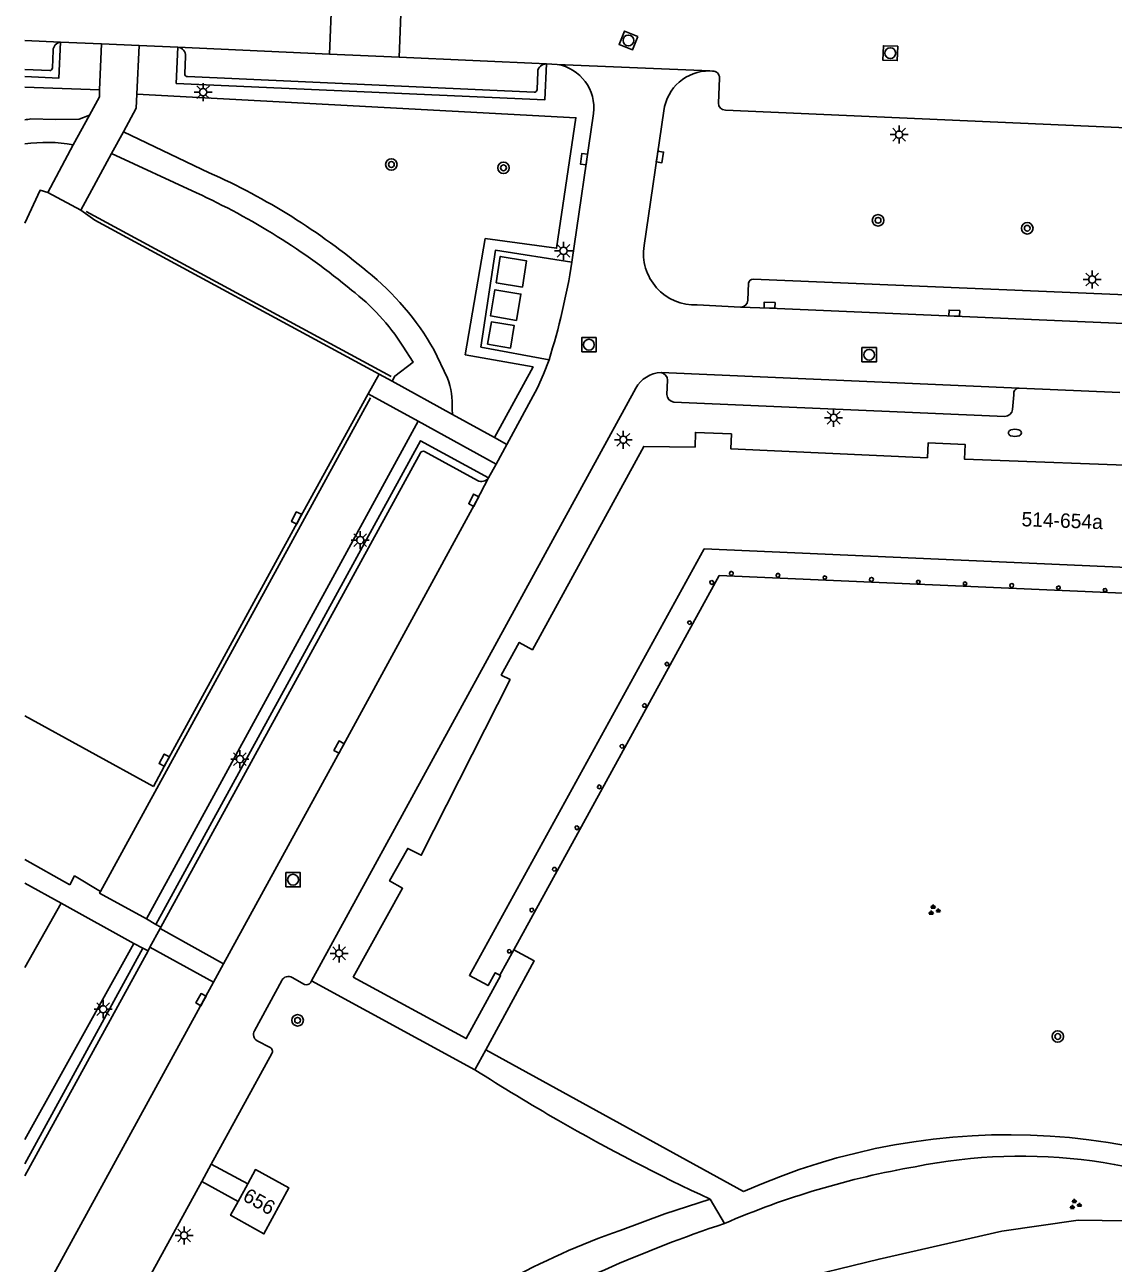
# Model space of a CAD drawing. Extents: x 132994 to 136000, y 393499 to 395512.
# Drawn here: x 133000 to 133075.7, y 395099.1 to 395185.2 of the extents above; entities that cross this region are included whole.
import ezdxf

# ---------------------------------------------------------------- set-up
doc = ezdxf.new("R2010")
doc.units = 0
for name, color, linetype in [('gg-afsc-hekwerk', 7, 'Continuous'), ('gg-anno-huisnummerreeks BGT', 7, 'Continuous'), ('gg-bbg-hoofdgebouw', 7, 'Continuous'), ('gg-bbg-onder overbouw', 7, 'Continuous'), ('gg-bbg-pand overbouw', 7, 'Continuous'), ('gg-bbg-pilaar onder overbouw', 7, 'Continuous'), ('gg-knt-verharding', 7, 'Continuous'), ('gg-knt-verharding nz', 7, 'Continuous'), ('gg-kntw-bovenkant insteek waterloop', 7, 'Continuous'), ('gg-kwrk-afval apart plaats', 7, 'Continuous'), ('gt-grn-groengrens', 7, 'Continuous'), ('gt-grn-weggrens', 7, 'Continuous'), ('gt-symb-boom', 7, 'Continuous'), ('gt-symb-brandkraan', 7, 'Continuous'), ('gt-symb-groenvak', 7, 'Continuous'), ('gt-symb-kolk', 7, 'Continuous'), ('gt-symb-lichtmast', 7, 'Continuous'), ('gt-symb-rioolschacht', 7, 'Continuous')]:
    doc.layers.add(name, color=color, linetype=linetype)

# ---------------------------------------------------------------- blocks, each defined once
blk = doc.blocks.new('gt0-BOOM')
at = {"layer": 'gt-symb-boom'}
for radius in [0.4, 0.2]:
    blk.add_circle((0, 0), radius, dxfattribs=at)
blk = doc.blocks.new('gt0-RS')
at = {"layer": 'gt-symb-rioolschacht'}
blk.add_lwpolyline([(-0.5, -0.5), (0.5, -0.5), (0.5, 0.5), (-0.5, 0.5)], close=True, dxfattribs=at)
blk.add_circle((0, 0), 0.375, dxfattribs=at)
blk = doc.blocks.new('gt0-KOLK')
at = {"layer": 'gt-symb-kolk'}
blk.add_lwpolyline([(0, 0), (0.375, 0), (0.375, 0.4), (-0.375, 0.4), (-0.375, 0), (0, 0)], dxfattribs=at)
blk = doc.blocks.new('gt0-LMAST')
at = {"layer": 'gt-symb-lichtmast'}
for p, q in [((-0.182, 0.173), (-0.447, 0.438)), ((-0.005, 0.246), (-0.005, 0.621)), ((0.172, 0.173), (0.437, 0.438)), ((-0.255, -0.004), (-0.63, -0.004)), ((-0.182, -0.181), (-0.447, -0.446)), ((-0.005, -0.254), (-0.005, -0.629)), ((0.437, -0.446), (0.172, -0.181)), ((0.245, -0.004), (0.62, -0.004))]:
    blk.add_line(p, q, dxfattribs=at)
blk.add_circle((-0.005, -0.004), 0.25, dxfattribs=at)
blk = doc.blocks.new('gt0-BR')
at = {"layer": 'gt-symb-brandkraan'}
for centre, radius, start, end in [((-0.244, 0), 0.206, 107.56694, 252.43307), ((0.599, -2.664), 3, 106.89205, 107.56694), ((0, -0.691), 0.938, 73.10799, 106.89205), ((-0.599, -2.664), 3, 72.43309, 73.10799), ((0.244, 0), 0.206, 287.56695, 72.43309), ((0.599, 2.664), 3, 252.43307, 253.10797), ((0, 0.691), 0.938, 253.10797, 286.89206), ((-0.599, 2.664), 3, 286.89206, 287.56695)]:
    blk.add_arc(centre, radius, start, end, dxfattribs=at)
blk = doc.blocks.new('gt0-GRVAK')
at = {"layer": 'gt-symb-groenvak'}
for p, q in [((-0.11, 0.189), (-0.228, 0.24)), ((-0.182, 0.153), (0.088, 0.153)), ((-0.091, 0.211), (-0.156, 0.322)), ((-0.047, 0.214), (-0.047, 0.393)), ((-0.004, 0.211), (0.061, 0.322)), ((0.015, 0.189), (0.133, 0.24)), ((0.262, -0.052), (0.197, 0.059)), ((0.305, -0.049), (0.305, 0.13)), ((0.349, -0.052), (0.414, 0.059)), ((-0.245, -0.228), (-0.363, -0.177)), ((-0.318, -0.264), (-0.047, -0.264)), ((-0.226, -0.206), (-0.291, -0.095)), ((-0.183, -0.203), (-0.183, -0.024)), ((-0.139, -0.206), (-0.074, -0.095)), ((-0.12, -0.228), (-0.002, -0.177)), ((0.243, -0.074), (0.125, -0.023)), ((0.17, -0.11), (0.441, -0.11)), ((0.368, -0.074), (0.486, -0.023))]:
    blk.add_line(p, q, dxfattribs=at)

msp = doc.modelspace()

# ---------------------------------------------------------------- linework, layer by layer
at = {"layer": 'gg-afsc-hekwerk'}
for p, q in [((133025.474, 395160.771), (133004.267, 395172.22)), ((133005.27, 395124.983), (133024.044, 395159.285)), ((133000, 395127.185), (133003.124, 395125.446))]:
    msp.add_line(p, q, dxfattribs=at)
at = {"layer": 'gg-bbg-hoofdgebouw'}
msp.add_line((133014.838, 395103.44), (133015.497, 395104.651), dxfattribs=at)
for points in [[(133078.98, 395154.5), (133065.33, 395155.01), (133065.37, 395156.04), (133062.8, 395156.14), (133062.75, 395155.11), (133049.08, 395155.74), (133049.13, 395156.77), (133046.62, 395156.88), (133046.6, 395155.85), (133043.03, 395155.9), (133035.29, 395141.77), (133034.38, 395142.28), (133033.13, 395140.01), (133033.74, 395139.7), (133027.56, 395127.49), (133026.62, 395127.97), (133025.36, 395125.71), (133026.26, 395125.2), (133022.83, 395119.03)], [(133033.025, 395119.153), (133033.081, 395119.122), (133030.694, 395114.746), (133022.83, 395119.03)], [(133015.497, 395104.651), (133016.04, 395105.65), (133018.35, 395104.39), (133016.62, 395101.18), (133014.311, 395102.47), (133014.838, 395103.44)]]:
    msp.add_lwpolyline(points, dxfattribs=at)
at = {"layer": 'gg-bbg-onder overbouw'}
msp.add_lwpolyline([(133108.047, 395115.865), (133108.381, 395116.009), (133108.775, 395115.09), (133110.117, 395115.666), (133108.342, 395119.716), (133096.637, 395146.616), (133047.236, 395148.781), (133030.913, 395119.145), (133032.209, 395118.431), (133032.704, 395119.33), (133033.025, 395119.153)], dxfattribs=at)
at = {"layer": 'gg-bbg-pand overbouw'}
msp.add_line((133033.025, 395119.153), (133033.99, 395120.909), dxfattribs=at)
msp.add_lwpolyline([(133033.99, 395120.909), (133048.281, 395146.92), (133095.419, 395144.881), (133107.382, 395117.393)], dxfattribs=at)
at = {"layer": 'gg-bbg-pilaar onder overbouw'}
for points in [[(133047.773, 395146.583), (133047.849, 395146.547), (133047.889, 395146.473), (133047.854, 395146.355), (133047.78, 395146.315), (133047.662, 395146.35), (133047.621, 395146.466), (133047.657, 395146.542), (133047.773, 395146.583)], [(133048.985, 395147.101), (133049.055, 395147.202), (133049.137, 395147.217), (133049.238, 395147.147), (133049.241, 395147.025), (133049.183, 395146.964), (133049.061, 395146.961), (133049, 395147.019), (133048.985, 395147.101)], [(133052.492, 395146.926), (133052.423, 395146.826), (133052.301, 395146.823), (133052.241, 395146.88), (133052.226, 395146.962), (133052.295, 395147.062), (133052.417, 395147.065), (133052.477, 395147.008), (133052.492, 395146.926)], [(133055.742, 395146.765), (133055.677, 395146.671), (133055.53, 395146.691), (133055.503, 395146.836), (133055.594, 395146.906), (133055.728, 395146.842), (133055.742, 395146.765)], [(133058.991, 395146.643), (133058.954, 395146.566), (133058.835, 395146.524), (133058.758, 395146.561), (133058.717, 395146.636), (133058.753, 395146.757), (133058.872, 395146.799), (133058.949, 395146.762), (133058.991, 395146.643)], [(133062.235, 395146.466), (133062.201, 395146.396), (133062.092, 395146.357), (133061.984, 395146.46), (133062.049, 395146.594), (133062.196, 395146.575), (133062.235, 395146.466)], [(133065.468, 395146.426), (133065.486, 395146.35), (133065.389, 395146.238), (133065.253, 395146.295), (133065.265, 395146.442), (133065.371, 395146.486), (133065.468, 395146.426)], [(133068.737, 395146.271), (133068.713, 395146.152), (133068.643, 395146.106), (133068.524, 395146.13), (133068.473, 395146.241), (133068.533, 395146.348), (133068.613, 395146.37), (133068.691, 395146.341), (133068.737, 395146.271)], [(133071.985, 395146.127), (133071.99, 395146.047), (133071.871, 395145.951), (133071.763, 395145.999), (133071.734, 395146.074), (133071.755, 395146.152), (133071.898, 395146.207), (133071.985, 395146.127)], [(133075.211, 395145.982), (133075.215, 395145.865), (133075.081, 395145.792), (133074.971, 395145.896), (133075.004, 395146.009), (133075.153, 395146.037), (133075.211, 395145.982)], [(133046.337, 395143.639), (133046.303, 395143.567), (133046.193, 395143.528), (133046.083, 395143.632), (133046.148, 395143.768), (133046.298, 395143.749), (133046.337, 395143.639)], [(133044.535, 395140.847), (133044.639, 395140.902), (133044.763, 395140.814), (133044.718, 395140.669), (133044.602, 395140.649), (133044.511, 395140.771), (133044.535, 395140.847)], [(133043.188, 395137.838), (133043.13, 395137.783), (133043.012, 395137.787), (133042.957, 395137.845), (133042.947, 395137.925), (133043.058, 395138.029), (133043.192, 395137.956), (133043.188, 395137.838)], [(133041.39, 395135.027), (133041.39, 395135.108), (133041.438, 395135.174), (133041.556, 395135.193), (133041.641, 395135.108), (133041.641, 395135.027), (133041.593, 395134.961), (133041.475, 395134.942), (133041.39, 395135.027)], [(133039.855, 395132.342), (133039.93, 395132.373), (133040.061, 395132.292), (133040.025, 395132.142), (133039.95, 395132.111), (133039.84, 395132.157), (133039.809, 395132.232), (133039.855, 395132.342)], [(133038.386, 395129.532), (133038.495, 395129.476), (133038.521, 395129.397), (133038.495, 395129.317), (133038.386, 395129.261), (133038.276, 395129.317), (133038.257, 395129.438), (133038.306, 395129.506), (133038.386, 395129.532)], [(133036.885, 395126.644), (133036.941, 395126.582), (133036.935, 395126.46), (133036.873, 395126.404), (133036.79, 395126.395), (133036.695, 395126.472), (133036.701, 395126.594), (133036.763, 395126.65), (133036.885, 395126.644)], [(133035.244, 395123.822), (133035.322, 395123.797), (133035.37, 395123.731), (133035.37, 395123.649), (133035.285, 395123.564), (133035.203, 395123.564), (133035.137, 395123.612), (133035.137, 395123.768), (133035.244, 395123.822)], [(133033.607, 395120.919), (133033.723, 395120.94), (133033.808, 395120.858), (133033.764, 395120.712), (133033.611, 395120.709), (133033.561, 395120.853), (133033.607, 395120.919)]]:
    msp.add_lwpolyline(points, dxfattribs=at)
at = {"layer": 'gg-knt-verharding'}
for p, q in [((133021.424, 395188.984), (133021.189, 395183.16)), ((133026.023, 395182.955), (133026.266, 395188.757)), ((133000, 395184.106), (133002.484, 395183.997)), ((133002.484, 395183.997), (133005.332, 395183.878)), ((133005.207, 395180.675), (133005.332, 395183.878)), ((133005.332, 395183.878), (133007.964, 395183.763)), ((133007.964, 395183.763), (133007.8, 395180.384)), ((133007.964, 395183.763), (133010.645, 395183.642)), ((133010.645, 395183.642), (133021.189, 395183.16)), ((133001.922, 395182.21), (133001.966, 395183.417)), ((133011.178, 395183.022), (133011.124, 395181.79)), ((133021.189, 395183.16), (133026.023, 395182.955)), ((133026.023, 395182.955), (133036.26, 395182.483)), ((133000, 395182.1), (133001.735, 395182.024)), ((133035.617, 395180.708), (133035.656, 395181.943)), ((133036.26, 395182.483), (133037.017, 395182.451)), ((133037.017, 395182.451), (133047.625, 395181.995)), ((133047.807, 395181.987), (133047.625, 395181.995)), ((133011.302, 395181.596), (133035.407, 395180.511)), ((133048.289, 395181.5), (133048.221, 395179.761)), ((133004.498, 395178.912), (133003.361, 395176.869)), ((133038.033, 395168.697), (133039.542, 395179.044)), ((133044.426, 395179.225), (133043.053, 395169.855)), ((133048.702, 395179.263), (133099.188, 395177.053)), ((133006.861, 395177.758), (133006.022, 395176.249)), ((133006.861, 395177.758), (133012.83, 395174.918)), ((133003.361, 395176.869), (133001.594, 395173.545)), ((133006.022, 395176.249), (133003.893, 395172.308)), ((133006.022, 395176.249), (133011.937, 395173.517)), ((133003.893, 395172.308), (133001.594, 395173.545)), ((133050.276, 395166.054), (133050.32, 395167.245)), ((133050.627, 395167.533), (133097.55, 395165.532)), ((133046.738, 395165.731), (133049.764, 395165.575)), ((133028.44, 395162.628), (133029.382, 395160.65)), ((133024.64, 395160.922), (133023.874, 395159.556)), ((133024.64, 395160.922), (133025.534, 395160.437)), ((133025.534, 395160.437), (133029.727, 395158.123)), ((133044.686, 395160.498), (133044.646, 395159.518)), ((133019.939, 395118.762), (133042.489, 395159.941)), ((133023.874, 395159.556), (133027.339, 395157.646)), ((133068.676, 395158.456), (133068.761, 395159.492)), ((133069.131, 395159.96), (133076.121, 395159.646)), ((133045.115, 395158.987), (133068.137, 395157.991)), ((133029.712, 395158.486), (133029.727, 395158.123)), ((133029.727, 395158.123), (133032.666, 395156.523)), ((133027.339, 395157.646), (133032.771, 395154.673)), ((133032.666, 395156.523), (133033.51, 395156.036)), ((133032.771, 395154.673), (133033.51, 395156.036)), ((133009.46, 395122.485), (133027.507, 395155.45)), ((133027.789, 395155.547), (133031.469, 395153.524)), ((133032.237, 395153.707), (133032.771, 395154.673)), ((133000, 395137.182), (133008.958, 395132.275)), ((133000, 395125.553), (133002.54, 395124.155)), ((133000, 395119.68), (133002.54, 395124.155)), ((133002.54, 395124.155), (133007.586, 395121.365)), ((133009.112, 395122.69), (133008.452, 395123.08)), ((133009.112, 395122.69), (133009.46, 395122.485)), ((133009.408, 395122.391), (133009.46, 395122.485)), ((133008.69, 395121.1), (133009.408, 395122.391)), ((133000, 395106.049), (133008.209, 395121.041)), ((133000, 395105.209), (133008.571, 395120.852)), ((133008.209, 395121.041), (133007.586, 395121.365)), ((133008.209, 395121.041), (133008.571, 395120.852)), ((133008.571, 395120.852), (133008.69, 395121.1)), ((133015.965, 395115.285), (133017.866, 395118.792)), ((133018.59, 395118.999), (133019.452, 395118.519)), ((133019.872, 395118.63), (133019.939, 395118.762)), ((133019.939, 395118.762), (133031.293, 395112.584)), ((133017.051, 395114.13), (133016.149, 395114.604)), ((133031.293, 395112.584), (133032.047, 395113.974)), ((133049.967, 395104.115), (133032.047, 395113.974)), ((133012.965, 395106.027), (133017.181, 395113.713)), ((133012.304, 395104.817), (133012.965, 395106.027)), ((133012.965, 395106.027), (133015.497, 395104.651)), ((133003.374, 395088.526), (133012.304, 395104.817)), ((133012.304, 395104.817), (133014.838, 395103.44))]:
    msp.add_line(p, q, dxfattribs=at)
for points in [[(133000, 395181.599), (133002.375, 395181.496), (133002.484, 395183.997)], [(133010.645, 395183.642), (133010.532, 395181.13), (133036.147, 395179.977), (133036.26, 395182.483)], [(133004.498, 395178.912), (133005.189, 395180.205), (133005.207, 395180.675)], [(133007.8, 395180.384), (133007.737, 395179.415), (133006.861, 395177.758)], [(133000.431, 395178.658), (133002.105, 395178.628), (133003.785, 395178.632), (133004.498, 395178.912)], [(133000, 395171.413), (133001.07, 395173.706), (133001.594, 395173.545)], [(133003.893, 395172.308), (133004.875, 395171.634), (133024.64, 395160.922)], [(133036.444, 395161.912), (133031.71, 395162.809), (133032.734, 395169.55), (133038.033, 395168.697)], [(133026.28, 395162.878), (133026.993, 395161.749), (133025.728, 395160.793), (133025.534, 395160.437)], [(133033.51, 395156.036), (133035.641, 395159.963), (133036.057, 395160.929), (133036.444, 395161.912)], [(133008.958, 395132.275), (133009.873, 395134), (133019.074, 395150.846), (133023.874, 395159.556)], [(133032.237, 395153.707), (133027.513, 395156.293), (133009.112, 395122.69)], [(133003.124, 395125.446), (133003.459, 395126.049), (133005.27, 395124.983)], [(133005.27, 395124.983), (133005.204, 395124.862), (133008.452, 395123.08)], [(133032.047, 395113.974), (133035.401, 395120.154), (133033.99, 395120.909)], [(133047.638, 395103.593), (133044.485, 395102.574), (133041.38, 395101.418)]]:
    msp.add_lwpolyline(points, dxfattribs=at)
for centre, radius, start, end in [((133002.577, 395183.392), 0.612, 98.77403, 177.68967), ((133010.581, 395183.048), 0.597, 357.47696, 83.89285), ((133001.747, 395182.199), 0.175, 266.09789, 3.5949), ((133036.25, 395181.887), 0.596, 88.99169, 174.60426), ((133036.506, 395179.433), 3.06, 352.68977, 80.39609), ((133047.58, 395178.814), 3.181, 89.19583, 172.58246), ((133047.83, 395181.528), 0.46, 356.54588, 92.86283), ((133011.326, 395181.797), 0.202, 181.90812, 263.16624), ((133035.39, 395180.74), 0.23, 274.34819, 351.99288), ((133048.722, 395179.763), 0.501, 180.27015, 267.74021), ((133003.696, 395156.567), 22.331, 98.40604, 99.52556), ((133001.525, 395166.423), 10.606, 80.03017, 98.26523), ((132993.855, 395132.382), 46.576, 49.98354, 65.95878), ((132991.878, 395129.488), 48.383, 50.4046, 65.50727), ((133046.599, 395169.315), 3.587, 171.34973, 272.21503), ((132991.619, 395175.988), 46.983, 342.56628, 351.07226), ((133011.882, 395153.171), 19.069, 29.73147, 51.30042), ((133050.628, 395167.225), 0.308, 90.11244, 176.22958), ((133013.35, 395154.616), 15.344, 32.57905, 52.38315), ((133049.756, 395166.096), 0.521, 270.85003, 355.33552), ((133024.674, 395158.825), 5.049, 356.15147, 21.18961), ((133044.272, 395159.023), 2.005, 91.16213, 152.76582), ((133044.125, 395160.476), 0.562, 2.20803, 79.08352), ((133045.165, 395159.504), 0.52, 178.46979, 264.43461), ((133069.134, 395159.577), 0.383, 90.42775, 192.91257), ((133068.128, 395158.546), 0.555, 270.90465, 350.6646), ((133027.695, 395155.363), 0.207, 62.89531, 155.06822), ((133031.743, 395154.079), 0.618, 243.73628, 323.06889), ((133018.33, 395118.54), 0.528, 60.41591, 151.49579), ((133019.595, 395118.83), 0.342, 245.36783, 324.24013), ((133016.412, 395115.04), 0.51, 151.32263, 238.91691), ((133016.918, 395113.86), 0.301, 330.85007, 63.77973), ((133107.18, 395231.218), 140.829, 237.39381, 240.16153), ((133107.294, 395231.391), 141.036, 240.15638, 244.97669), ((133068.402, 395063.106), 44.962, 58.46761, 114.20508), ((133069.249, 395069.362), 37.217, 63.27641, 101.40004), ((133071.891, 395048.006), 58.696, 99.80767, 113.33439), ((133078.039, 395013.41), 93.246, 108.37689, 119.34041), ((133058.016, 395053.638), 50.593, 109.19747, 119.13762)]:
    msp.add_arc(centre, radius, start, end, dxfattribs=at)
at = {"layer": 'gg-knt-verharding nz'}
for p, q in [((133044.231, 395161.028), (133069.131, 395159.96)), ((133013.824, 395119.949), (133009.408, 395122.391)), ((133013.13, 395118.661), (133008.69, 395121.1)), ((133013.824, 395119.949), (133013.13, 395118.661))]:
    msp.add_line(p, q, dxfattribs=at)
for points in [[(133049.764, 395165.575), (133051.766, 395165.518), (133081.234, 395164.232), (133094.043, 395163.691), (133098.19, 395163.501)], [(133032.237, 395153.707), (133031.388, 395152.07), (133022.027, 395134.914), (133013.824, 395119.949)], [(133000, 395094.731), (133000.965, 395096.461), (133013.13, 395118.661)]]:
    msp.add_lwpolyline(points, dxfattribs=at)
at = {"layer": 'gg-kntw-bovenkant insteek waterloop'}
msp.add_lwpolyline([(133036.168, 395092.184), (133039.175, 395094.064), (133045.393, 395096.535), (133052.94, 395097.851), (133059.395, 395099.43), (133067.927, 395101.357), (133073.238, 395102.125), (133079.892, 395102.047), (133091.095, 395098.88), (133094.765, 395097.89), (133107.441, 395091.762), (133109.133, 395088.35), (133110.035, 395084.632), (133110.498, 395081.08), (133109.758, 395079.009), (133107.449, 395076.609), (133104.551, 395075.502), (133091.406, 395074.184), (133078.697, 395074.39), (133068.124, 395075.368), (133057.177, 395076.651)], dxfattribs=at)
at = {"layer": 'gg-kwrk-afval apart plaats'}
for points in [[(133032.771, 395167.275), (133033.057, 395169.103), (133034.886, 395168.796), (133034.6, 395166.968), (133032.771, 395167.275)], [(133034.187, 395164.662), (133032.384, 395164.97), (133032.687, 395166.79), (133034.491, 395166.482), (133034.187, 395164.662)], [(133032.177, 395162.999), (133032.448, 395164.564), (133034.03, 395164.301), (133033.759, 395162.735), (133032.177, 395162.999)]]:
    msp.add_lwpolyline(points, dxfattribs=at)
at = {"layer": 'gt-grn-groengrens'}
for p, q in [((133000, 395180.868), (133005.207, 395180.675)), ((133008.452, 395123.08), (133027.339, 395157.646)), ((133000, 395107.741), (133007.586, 395121.365))]:
    msp.add_line(p, q, dxfattribs=at)
msp.add_lwpolyline([(133007.8, 395180.384), (133038.315, 395178.738), (133036.971, 395169.668), (133032.012, 395170.349), (133030.616, 395162.275), (133035.342, 395161.427), (133032.666, 395156.523)], dxfattribs=at)
at = {"layer": 'gt-grn-weggrens'}
msp.add_line((133048.642, 395101.901), (133047.638, 395103.593), dxfattribs=at)

# ---------------------------------------------------------------- block references
at = {"layer": 'gt-symb-boom'}
for p in [(133025.485, 395175.49), (133033.283, 395175.259), (133059.317, 395171.612), (133069.691, 395171.059), (133018.967, 395116.019), (133071.811, 395114.894)]:
    msp.add_blockref('gt0-BOOM', p, dxfattribs=at)
at = {"layer": 'gt-symb-brandkraan'}
msp.add_blockref('gt0-BR', (133068.832, 395156.842), dxfattribs=at)
at = {"layer": 'gt-symb-groenvak'}
for p in [(133063.2, 395123.669), (133073.01, 395103.218)]:
    msp.add_blockref('gt0-GRVAK', p, dxfattribs=at)
at = {"layer": 'gt-symb-kolk'}
for p, rotation in [((133039.076, 395175.83), 81.75691987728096), ((133043.954, 395176.045), -98.28416891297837), ((133051.766, 395165.518), -2.486398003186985), ((133064.609, 395164.96), -2.5105853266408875), ((133031.388, 395152.07), 62.57597352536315), ((133019.074, 395150.846), 65.10255076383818), ((133022.027, 395134.914), 61.38116837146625), ((133009.873, 395134), 61.35926906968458), ((133012.426, 395117.363), 61.51834243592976)]:
    msp.add_blockref('gt0-KOLK', p, dxfattribs=dict(at, rotation=rotation))
at = {"layer": 'gt-symb-lichtmast'}
for p in [(133012.401, 395180.523), (133060.782, 395177.571), (133037.456, 395169.497), (133074.215, 395167.504), (133056.237, 395157.897), (133041.616, 395156.372), (133023.33, 395149.394), (133014.965, 395134.175), (133021.853, 395120.678), (133005.449, 395116.79), (133011.077, 395101.079)]:
    msp.add_blockref('gt0-LMAST', p, dxfattribs=at)
at = {"layer": 'gt-symb-rioolschacht'}
for p, rotation in [((133041.964, 395184.111), 157.97515406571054), ((133060.168, 395183.231), 177.7643631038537)]:
    msp.add_blockref('gt0-RS', p, dxfattribs=dict(at, rotation=rotation))
for p in [(133039.218, 395162.969), (133058.701, 395162.268), (133018.651, 395125.79)]:
    msp.add_blockref('gt0-RS', p, dxfattribs=at)

# ---------------------------------------------------------------- texts
at = {"layer": 'gg-anno-huisnummerreeks BGT'}
for s, rotation, p in [('514-654a', 357.9, (133069.279, 395150.357)), ('656', 330.8, (133015.087, 395103.538))]:
    msp.add_text(s, height=1, rotation=rotation, dxfattribs=at).set_placement(p)

doc.saveas('drawing.dxf')
